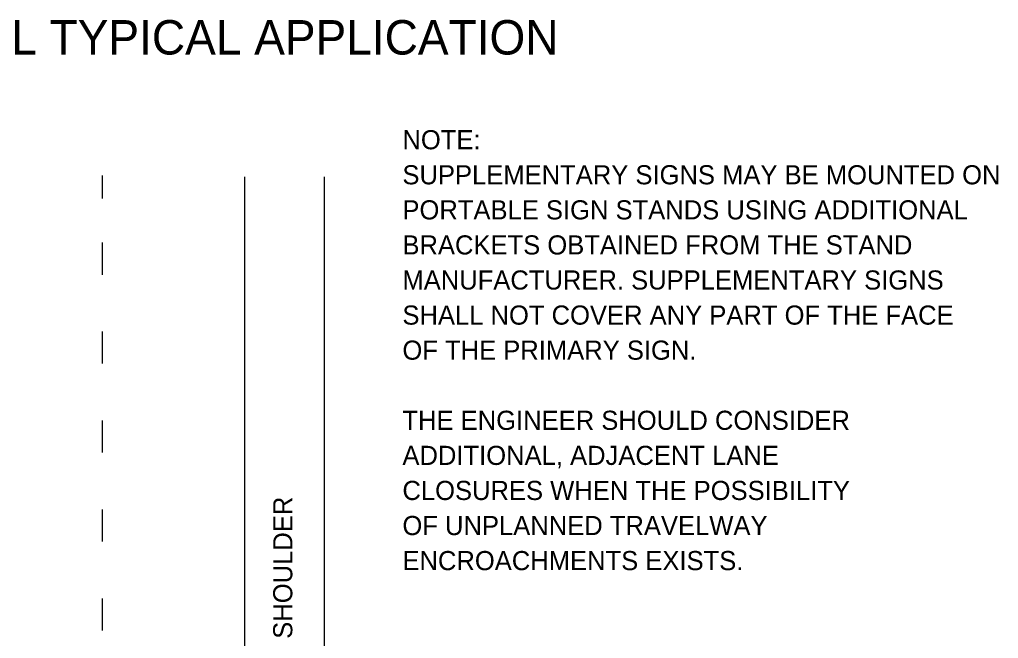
# Model space of a CAD drawing. Extents: x 1531.93 to 1538.58, y 1529.59 to 1539.24.
# Drawn here: x 1534.999 to 1538.071, y 1537.297 to 1539.237 of the extents above; entities that cross this region are included whole.
import ezdxf

# ---------------------------------------------------------------- set-up
doc = ezdxf.new("R2010")
doc.units = 0
for name, color, linetype in [('DETL-LINE', 7, 'Continuous'), ('DETL-NOTE', 7, 'Continuous'), ('DETL-TITL', 7, 'Continuous')]:
    doc.layers.add(name, color=color, linetype=linetype)

msp = doc.modelspace()

# ---------------------------------------------------------------- linework, layer by layer
at = {"layer": 'DETL-LINE'}
for p, q in [((1535.2599, 1538.6759), (1535.2599, 1538.7482)), ((1535.7048, 1538.7445), (1535.7048, 1531.7359)), ((1535.9548, 1538.7445), (1535.9548, 1534.3888)), ((1535.2599, 1538.4373), (1535.2599, 1538.5382)), ((1535.2599, 1538.1583), (1535.2599, 1538.2592)), ((1535.2599, 1537.8793), (1535.2599, 1537.9802)), ((1535.2599, 1537.6002), (1535.2599, 1537.7011)), ((1535.2599, 1537.3212), (1535.2599, 1537.4221))]:
    msp.add_line(p, q, dxfattribs=at)

# ---------------------------------------------------------------- texts
at = {"layer": 'DETL-NOTE'}
for s, p in [('NOTE:', (1536.2006, 1538.8307)), ('SUPPLEMENTARY SIGNS MAY BE MOUNTED ON ', (1536.2006, 1538.7207)), ('PORTABLE SIGN STANDS USING ADDITIONAL ', (1536.2006, 1538.6107)), ('BRACKETS OBTAINED FROM THE STAND ', (1536.2006, 1538.5007)), ('MANUFACTURER. SUPPLEMENTARY SIGNS ', (1536.2006, 1538.3907)), ('SHALL NOT COVER ANY PART OF THE FACE ', (1536.2006, 1538.2807)), ('OF THE PRIMARY SIGN.', (1536.2006, 1538.1707)), ('THE ENGINEER SHOULD CONSIDER', (1536.2006, 1537.9507)), ('ADDITIONAL, ADJACENT LANE', (1536.2006, 1537.8407)), ('CLOSURES WHEN THE POSSIBILITY', (1536.2006, 1537.7307)), ('OF UNPLANNED TRAVELWAY', (1536.2006, 1537.6207)), ('ENCROACHMENTS EXISTS.', (1536.2006, 1537.5107))]:
    msp.add_text(s, height=0.06, dxfattribs=at).set_placement(p)
msp.add_text('SHOULDER', height=0.06, rotation=90, dxfattribs=at).set_placement((1535.8551, 1537.2954))
at = {"layer": 'DETL-TITL'}
msp.add_text('TEMPORARY TRAFFIC CONTROL TYPICAL APPLICATION', height=0.108, dxfattribs=at).set_placement((1532.7424, 1539.1278))

doc.saveas('drawing.dxf')
